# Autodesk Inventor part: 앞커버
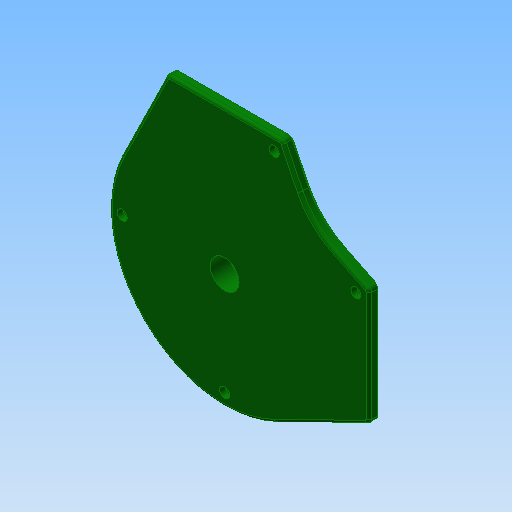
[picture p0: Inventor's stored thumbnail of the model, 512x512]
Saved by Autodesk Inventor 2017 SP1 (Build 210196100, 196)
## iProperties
Created: 2017-05
Part Number: 앞커버
Material: 알루미늄 6061
Document SubType Name: Modeling
Designer: mduedu
Density: 2.71 g/cm^3
Mass: 725.228 g
Surface Area: 595.074 cm^2
Volume: 267.612 cm^3
Appearance: 진녹색
Author: mduedu
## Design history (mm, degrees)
sketch "스케치1"
  geometry: L1 (-71.801, 35.28)-(-40, 100); L2 (-40, 100)-(40, 100); L3 (40, 100)-(52.248, 75.073); L4 (35.28, 71.801)-(59.768, 59.768); L5 (100, 40)-(100, -40); L6 (100, -40)-(35.28, -71.801); L7 (75.073, 52.248)-(100, 40); L8 (59.768, 59.768)-(71.801, 35.28); L9 (33.075, -67.313)-(95, -36.886); L10 (95, -36.886)-(95, 36.886); L11 (95, 36.886)-(72.868, 47.76); L12 (47.76, 72.868)-(36.886, 95); L13 (36.886, 95)-(-36.886, 95); L14 (-36.886, 95)-(-67.313, 33.075); A1 r 80 centre (0, 0) between (71.801, 35.28) and (-71.801, 35.28); A2 r 80 centre (0, 0) between (35.28, -71.801) and (71.801, 35.28); A3 r 80 centre (0, 0) between (-71.801, 35.28) and (35.28, -71.801); A4 r 50 centre (97.123, 97.123) between (52.248, 75.073) and (75.073, 52.248); A5 r 55 centre (97.123, 97.123) between (47.76, 72.868) and (72.868, 47.76); A6 r 75 centre (0, 0) between (-67.313, 33.075) and (33.075, -67.313); 3 further points
  constraints: 29 end point, 15 tangent, 14 point on circle, 6 centre point, 2 midpoint, 2 perpendicular, 2 point on line, 1 coincident, 1 horizontal, 1 horizontal alignment, 1 vertical alignment, 6 other
  dimensions: "d0" = 160 diameter of A1; "d1" = 100 distance from line of L2 point (0, 0); "d2" = 100 distance from line of L5 point (0, 0); "d3" = 80 distance of L1.end L2.end; "d4" = 80 distance of L5.start L5.end; "d5" = 50 radius of A4; "d6" = 5 distance between parallel lines of L13 L2
extrude "돌출1" new body sketch "스케치1" distance "d7" = 5; taper "d8" = 0 deg
fillet "모깎기1" dims "d9" = 3
sketch "스케치2"
  geometry: C1 r 22 at (0, 0); 1 further point
  constraints: 1 centre point, 1 coincident
  dimensions: "d10" = 44 diameter of C1
extrude "돌출2" join sketch "스케치2" distance "d11" = 12.5; taper "d12" = 0 deg
sketch "스케치3"
  geometry: C1 r 18.5 at (0, 0); 1 further point
  constraints: 1 centre point, 1 coincident
  dimensions: "d13" = 37 diameter of C1
extrude "돌출3" cut sketch "스케치3" distance "d14" = 9; taper "d15" = 0 deg
sketch "스케치5"
  geometry: L1 (-67.313, 33.075)-(-37.71, 93.323) reference; L2 (-35.017, 95)-(35.017, 95) reference; L3 (37.71, 93.323)-(47.76, 72.868) reference; L4 (72.868, 47.76)-(93.323, 37.71) reference; L5 (95, 35.017)-(95, -35.017) reference; L6 (93.323, -37.71)-(33.075, -67.313) reference; L7 (93.323, 37.71)-(72.868, 47.76) reference; L8 (95, -35.017)-(95, 35.017) reference; L9 (35.017, 95)-(-35.017, 95) reference; L10 (47.76, 72.868)-(37.71, 93.323) reference; C1 r 4 at (-71, 0); C2 r 4 at (0, -71); C3 r 4 at (91, 34.394); C4 r 4 at (34.394, 91); A1 r 75 centre (0, 0) between (-67.313, 33.075) and (33.075, -67.313) reference; A2 r 3 centre (-35.017, 92) between (-35.017, 95) and (-37.71, 93.323) reference; A3 r 3 centre (35.017, 92) between (37.71, 93.323) and (35.017, 95) reference; A4 r 55 centre (97.123, 97.123) between (47.76, 72.868) and (72.868, 47.76) reference; A5 r 3 centre (92, 35.017) between (95, 35.017) and (93.323, 37.71) reference; A6 r 3 centre (92, -35.017) between (93.323, -37.71) and (95, -35.017) reference; A7 r 75 centre (0, 0) between (-67.313, 33.075) and (33.075, -67.313) reference; 5 further points
  constraints: 6 tangent, 4 centre point, 4 coincident, 3 equal radius, 1 horizontal alignment, 1 vertical alignment
  dimensions: "d39" = 8 diameter of C1
  node "절단 모서리 투영1"
sketch "스케치7"
  geometry: L1 (100, -38.131)-(100, 38.131) reference; L2 (98.323, 40.824)-(75.073, 52.248) reference; L3 (52.248, 75.073)-(40.824, 98.323) reference; L4 (38.131, 100)-(-38.131, 100) reference; L5 (-40.824, 98.323)-(-71.801, 35.28) reference; L6 (35.28, -71.801)-(98.323, -40.824) reference; L7 (35.017, 96)-(-35.017, 96) reference; L8 (48.658, 73.309)-(38.607, 93.764) reference; L9 (93.764, 38.607)-(73.309, 48.658) reference; L10 (96, -35.017)-(96, 35.017) reference; L11 (33.516, -68.211)-(93.764, -38.607) reference; L12 (-38.607, 93.764)-(-68.211, 33.516) reference; A1 r 3 centre (97, -38.131) between (98.323, -40.824) and (100, -38.131) reference; A2 r 3 centre (97, 38.131) between (100, 38.131) and (98.323, 40.824) reference; A3 r 50 centre (97.123, 97.123) between (52.248, 75.073) and (75.073, 52.248) reference; A4 r 3 centre (38.131, 97) between (40.824, 98.323) and (38.131, 100) reference; A5 r 3 centre (-38.131, 97) between (-38.131, 100) and (-40.824, 98.323) reference; A6 r 80 centre (0, 0) between (-71.801, 35.28) and (35.28, -71.801) reference; A7 r 4 centre (35.017, 92) between (38.607, 93.764) and (35.017, 96) reference; A8 r 54 centre (97.123, 97.123) between (48.658, 73.309) and (73.309, 48.658) reference; A9 r 4 centre (92, 35.017) between (96, 35.017) and (93.764, 38.607) reference; A10 r 4 centre (92, -35.017) between (93.764, -38.607) and (96, -35.017) reference; A11 r 76 centre (0, 0) between (-68.211, 33.516) and (33.516, -68.211) reference; A12 r 4 centre (-35.017, 92) between (-35.017, 96) and (-38.607, 93.764) reference; 1 further point
extrude "돌출4" join sketch "스케치7" distance "d47" = 6; taper "d48" = 0 deg
sketch "스케치6"
  geometry: 4 further points
  constraints: 4 other
hole "구멍2" sketch "스케치6" at (0, -71), (91, 34.394), (34.394, 91), (-71, 0) diameter "d40" = 3.4; stored, may be unused: countersink angle "d44" = 90 deg, drill point angle "d46" = 0 deg; dims "d41" = 6, "d42" = 7, "d43" = 4, "d45" = 8
hole "구멍1" diameter "d18" = 20; stored, may be unused: countersink angle "d22" = 90 deg, drill point angle "d24" = 118 deg; dims "d19" = 6, "d20" = 4, "d21" = 2, "d23" = 8, "d50" = 10, "d51" = 10
fillet "모깎기2" dims "d25" = 3
chamfer "모따기1" distance "d27" = 1; stored, may be unused: second distance "d28" = 2, angle "d29" = 45 deg
chamfer "모따기2" distance "d33" = 1; stored, may be unused: second distance "d34" = 2, angle "d35" = 45 deg
chamfer "모따기3" distance "d36" = 1; stored, may be unused: second distance "d37" = 2, angle "d38" = 45 deg
fillet "모깎기3" dims "d49" = 2
node "솔리드1"
node "참조1"
